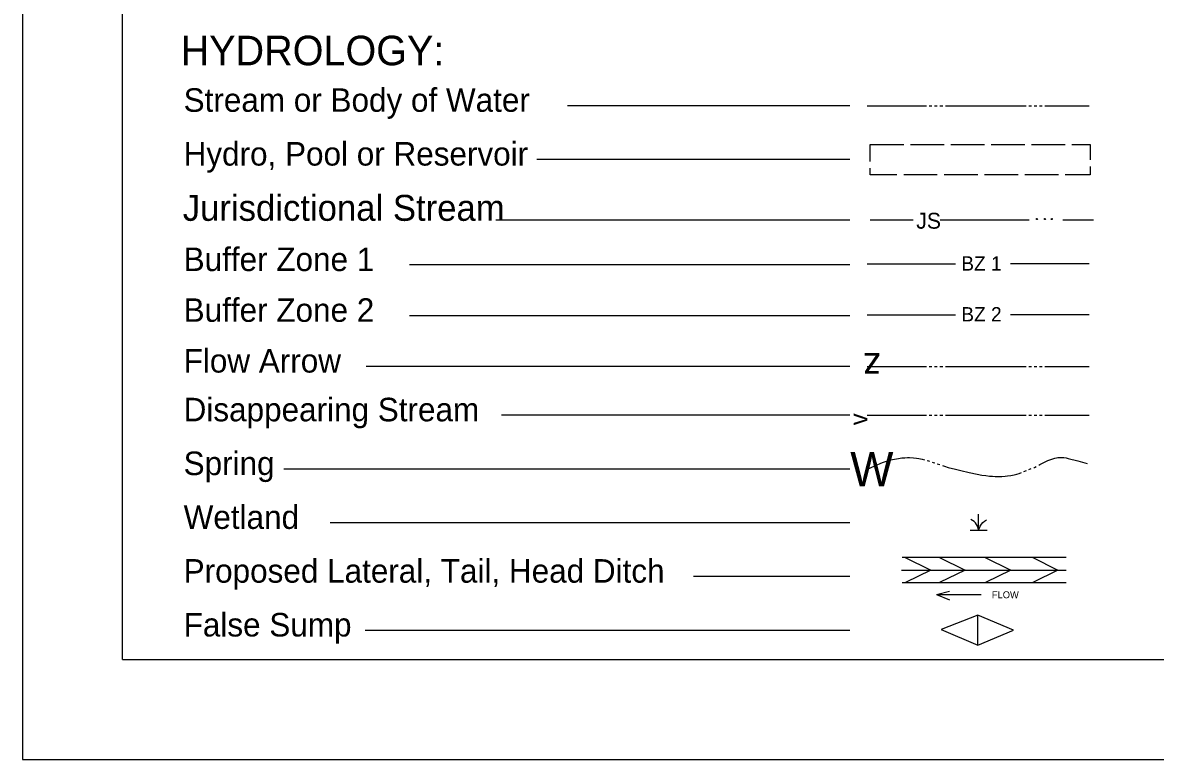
# Model space of a CAD drawing. Extents: x 1552903 to 1553044, y 811448 to 811540.
# Drawn here: x 1552902.56 to 1552937.98, y 811448.42 to 811471.45 of the extents above; entities that cross this region are included whole.
import ezdxf

# ---------------------------------------------------------------- set-up
doc = ezdxf.new("R2010")
doc.units = 0
for name, color, linetype in [('Exist DTM Breakline', 7, 'Continuous'), ('Exist Structure Major Bridge WW', 7, 'Continuous'), ('z - Construction', 7, 'Continuous')]:
    doc.layers.add(name, color=color, linetype=linetype)

msp = doc.modelspace()

# ---------------------------------------------------------------- linework, layer by layer
at = {"layer": 'Exist DTM Breakline'}
for p, q in [((1552928.427, 811468.851), (1552919.598, 811468.851)), ((1552928.974, 811468.851), (1552930.826, 811468.851)), ((1552930.91, 811468.851), (1552930.994, 811468.851)), ((1552931.078, 811468.851), (1552931.162, 811468.851)), ((1552931.246, 811468.851), (1552931.331, 811468.851)), ((1552931.415, 811468.851), (1552933.937, 811468.851)), ((1552934.021, 811468.851), (1552934.105, 811468.851)), ((1552934.189, 811468.851), (1552934.273, 811468.851)), ((1552934.357, 811468.851), (1552934.441, 811468.851)), ((1552934.526, 811468.851), (1552935.911, 811468.851)), ((1552929.064, 811467.639), (1552930.115, 811467.639)), ((1552929.064, 811467.109), (1552929.064, 811467.639)), ((1552930.325, 811467.639), (1552931.376, 811467.639)), ((1552931.586, 811467.639), (1552932.637, 811467.639)), ((1552932.847, 811467.639), (1552933.898, 811467.639)), ((1552934.108, 811467.639), (1552935.159, 811467.639)), ((1552928.427, 811467.17), (1552918.641, 811467.17)), ((1552931.163, 811466.686), (1552930.112, 811466.686)), ((1552932.425, 811466.686), (1552931.374, 811466.686)), ((1552933.686, 811466.686), (1552932.635, 811466.686)), ((1552934.947, 811466.686), (1552933.896, 811466.686)), ((1552928.427, 811465.27), (1552917.362, 811465.27)), ((1552928.427, 811463.873), (1552914.659, 811463.873)), ((1552928.974, 811463.909), (1552931.732, 811463.909)), ((1552935.911, 811463.909), (1552933.447, 811463.909)), ((1552928.427, 811462.286), (1552914.659, 811462.286)), ((1552928.974, 811462.314), (1552931.732, 811462.314)), ((1552935.911, 811462.314), (1552933.447, 811462.314)), ((1552928.427, 811460.7), (1552913.306, 811460.7)), ((1552928.974, 811460.7), (1552930.826, 811460.7)), ((1552930.91, 811460.7), (1552930.994, 811460.7)), ((1552931.078, 811460.7), (1552931.162, 811460.7)), ((1552931.246, 811460.7), (1552931.331, 811460.7)), ((1552931.415, 811460.7), (1552933.937, 811460.7)), ((1552934.021, 811460.7), (1552934.105, 811460.7)), ((1552934.189, 811460.7), (1552934.273, 811460.7)), ((1552934.357, 811460.7), (1552934.441, 811460.7)), ((1552934.526, 811460.7), (1552935.911, 811460.7)), ((1552928.427, 811459.176), (1552917.538, 811459.176)), ((1552928.974, 811459.176), (1552930.826, 811459.176)), ((1552930.91, 811459.176), (1552930.994, 811459.176)), ((1552931.078, 811459.176), (1552931.162, 811459.176)), ((1552931.246, 811459.176), (1552931.331, 811459.176)), ((1552931.415, 811459.176), (1552933.937, 811459.176)), ((1552934.021, 811459.176), (1552934.105, 811459.176)), ((1552934.189, 811459.176), (1552934.273, 811459.176)), ((1552934.357, 811459.176), (1552934.441, 811459.176)), ((1552934.526, 811459.176), (1552935.911, 811459.176)), ((1552931.161, 811457.659), (1552931.241, 811457.632)), ((1552928.427, 811457.495), (1552910.73, 811457.495)), ((1552933.869, 811457.413), (1552933.946, 811457.444)), ((1552934.025, 811457.475), (1552934.102, 811457.508)), ((1552932.452, 811455.585), (1552932.452, 811456.079)), ((1552928.427, 811455.813), (1552912.182, 811455.813)), ((1552932.186, 811455.585), (1552932.722, 811455.585)), ((1552930.065, 811454.741), (1552935.195, 811454.741)), ((1552930.141, 811454.741), (1552930.964, 811454.338)), ((1552931.21, 811454.741), (1552932.033, 811454.338)), ((1552932.635, 811454.741), (1552933.461, 811454.338)), ((1552934.126, 811454.741), (1552934.933, 811454.338)), ((1552928.427, 811454.132), (1552923.535, 811454.132)), ((1552930.043, 811454.338), (1552935.195, 811454.338)), ((1552930.964, 811454.338), (1552930.164, 811453.947)), ((1552932.033, 811454.338), (1552931.236, 811453.947)), ((1552933.461, 811454.338), (1552932.664, 811453.947)), ((1552934.933, 811454.338), (1552934.148, 811453.947)), ((1552930.065, 811453.947), (1552935.195, 811453.947)), ((1552931.137, 811453.568), (1552931.541, 811453.682)), ((1552931.137, 811453.568), (1552932.537, 811453.568)), ((1552931.137, 811453.568), (1552931.541, 811453.405)), ((1552932.425, 811452.922), (1552931.283, 811452.479)), ((1552932.425, 811451.993), (1552932.425, 811452.922)), ((1552933.544, 811452.458), (1552932.425, 811452.922)), ((1552928.427, 811452.45), (1552913.269, 811452.45)), ((1552931.283, 811452.479), (1552932.425, 811451.993)), ((1552932.425, 811451.993), (1552933.544, 811452.458))]:
    msp.add_line(p, q, dxfattribs=at)
for points in [[(1552935.369, 811467.639), (1552935.943, 811467.639), (1552935.943, 811467.161)], [(1552929.902, 811466.686), (1552929.064, 811466.686), (1552929.064, 811466.899)], [(1552935.943, 811466.951), (1552935.943, 811466.686), (1552935.157, 811466.686)], [(1552929.064, 811465.287), (1552930.409, 811465.287)], [(1552931.253, 811465.287), (1552932.432, 811465.287)], [(1552932.432, 811465.287), (1552934.03, 811465.287)], [(1552935.089, 811465.287), (1552936.049, 811465.287)], [(1552928.975, 811457.495), (1552929.214, 811457.595), (1552929.453, 811457.696), (1552929.513, 811457.719), (1552929.62, 811457.756), (1552929.702, 811457.778), (1552929.824, 811457.806), (1552929.948, 811457.828), (1552930.053, 811457.841), (1552930.145, 811457.848), (1552930.226, 811457.85), (1552930.297, 811457.85), (1552930.422, 811457.843), (1552930.516, 811457.833), (1552930.585, 811457.823), (1552930.689, 811457.803), (1552930.761, 811457.786)], [(1552930.843, 811457.764), (1552930.882, 811457.752), (1552930.923, 811457.74)], [(1552931.003, 811457.714), (1552931.037, 811457.702), (1552931.083, 811457.686)], [(1552934.332, 811457.613), (1552934.372, 811457.633), (1552934.537, 811457.719), (1552934.621, 811457.76), (1552934.708, 811457.795), (1552934.775, 811457.818), (1552934.833, 811457.832), (1552934.886, 811457.843), (1552934.932, 811457.85), (1552935.014, 811457.855), (1552935.075, 811457.855), (1552935.12, 811457.852), (1552935.188, 811457.843), (1552935.254, 811457.828), (1552935.552, 811457.746), (1552935.85, 811457.663)], [(1552931.321, 811457.604), (1552931.385, 811457.582), (1552931.503, 811457.547), (1552931.729, 811457.488), (1552931.899, 811457.444), (1552932.154, 811457.386), (1552932.412, 811457.332), (1552932.555, 811457.307), (1552932.681, 811457.288), (1552932.792, 811457.275), (1552932.89, 811457.267), (1552932.975, 811457.263), (1552933.051, 811457.261), (1552933.181, 811457.263), (1552933.279, 811457.269), (1552933.353, 811457.277), (1552933.461, 811457.293), (1552933.568, 811457.316), (1552933.649, 811457.338), (1552933.719, 811457.359), (1552933.79, 811457.385)], [(1552934.18, 811457.54), (1552934.197, 811457.547), (1552934.256, 811457.575)], [(1552932.452, 811455.585), (1552932.439, 811455.645), (1552932.422, 811455.704), (1552932.393, 811455.759), (1552932.355, 811455.809), (1552932.313, 811455.856), (1552932.262, 811455.889), (1552932.207, 811455.919)], [(1552932.452, 811455.585), (1552932.477, 811455.649), (1552932.507, 811455.712), (1552932.545, 811455.771), (1552932.591, 811455.822), (1552932.642, 811455.868), (1552932.697, 811455.91)]]:
    msp.add_lwpolyline(points, dxfattribs=at)
for centre in [(1552934.277, 811465.31), (1552934.526, 811465.31), (1552934.743, 811465.31)]:
    msp.add_ellipse(centre, major_axis=(0, 0.0166), ratio=0.938496, dxfattribs=at)
at = {"layer": 'Exist Structure Major Bridge WW'}
for q in [(1552905.688, 811536.962), (1553041.103, 811451.545)]:
    msp.add_line((1552905.688, 811451.545), q, dxfattribs=at)
at = {"layer": 'z - Construction'}
for p, q in [((1552902.563, 811540.087), (1552902.563, 811448.42)), ((1552902.563, 811448.42), (1553044.23, 811448.42))]:
    msp.add_line(p, q, dxfattribs=at)

# ---------------------------------------------------------------- texts
at = {"layer": 'Exist DTM Breakline'}
for s, height, p in [('HYDROLOGY:', 0.9249, (1552907.502, 811470.115)), ('Stream or Body of Water', 0.73569, (1552907.597, 811468.661)), ('Hydro, Pool or Reservoir', 0.73569, (1552907.597, 811466.98)), ('Jurisdictional Stream', 0.81102, (1552907.569, 811465.253)), ('JS', 0.4965, (1552930.503, 811465.007)), ('Buffer Zone 1', 0.73569, (1552907.597, 811463.683)), ('BZ 1', 0.4469, (1552931.912, 811463.698)), ('Buffer Zone 2', 0.73569, (1552907.597, 811462.096)), ('BZ 2', 0.4469, (1552931.912, 811462.109)), ('Flow Arrow', 0.7357, (1552907.597, 811460.51)), ('Disappearing Stream', 0.73569, (1552907.597, 811458.986)), ('Spring', 0.7357, (1552907.597, 811457.305)), ('W', 1.072, (1552928.439, 811456.959)), ('Wetland', 0.7357, (1552907.597, 811455.623)), ('Proposed Lateral, Tail, Head Ditch', 0.73569, (1552907.597, 811453.942)), ('FLOW', 0.218, (1552932.868, 811453.455)), ('False Sump', 0.7357, (1552907.597, 811452.26))]:
    msp.add_text(s, height=height, dxfattribs=at).set_placement(p)
for s, height, rotation, p in [('z', 0.841, 180, (1552929.396, 811461.12)), ('v', 0.555, 89.7591, (1552928.974, 811458.862))]:
    msp.add_text(s, height=height, rotation=rotation, dxfattribs=at).set_placement(p)

doc.saveas('drawing.dxf')
